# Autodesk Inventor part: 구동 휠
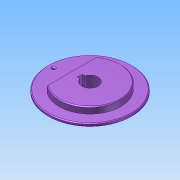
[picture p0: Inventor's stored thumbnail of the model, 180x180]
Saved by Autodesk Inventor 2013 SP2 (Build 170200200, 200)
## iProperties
Created: 2025-09
Part Number: 구동 휠
Material: Generic
Document SubType Name: Modeling
Designer: a
Density: 1 g/cm^3
Author: a
변환 표준: STEP AP214IS
전처리기: Build: 200, Release: 2013 SP2 Update 6 - Date: Thu 07/17/2014
전송 단위: 밀리미터
불확실성: 0.01
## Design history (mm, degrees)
node "구동 휠1"
node "솔리드1"
node "기준1"
